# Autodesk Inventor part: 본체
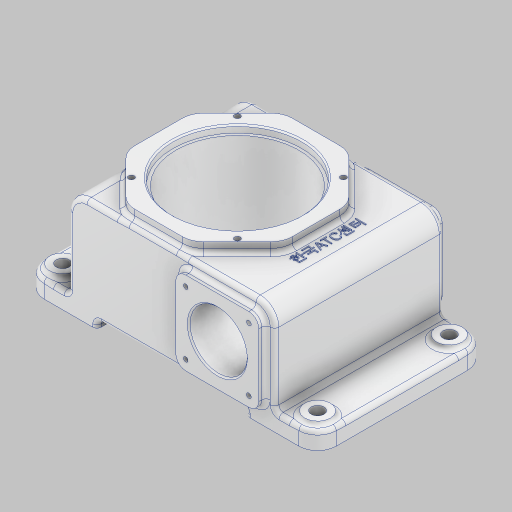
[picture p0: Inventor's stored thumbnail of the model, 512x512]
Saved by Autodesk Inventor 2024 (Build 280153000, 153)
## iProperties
Created: 2026-02
Part Number: 본체
Material: 알루미늄 6061
Document SubType Name: Modeling
Designer: 2-10
Density: 2.7 g/cm^3
Appearance: 알루미늄 - 평지
Mass: 2338.38 g
Surface Area: 1210.62 cm^2
Volume: 866.066 cm^3
Author: 2-10
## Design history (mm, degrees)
sketch "스케치1"
  geometry: L1 (-72, -35)-(72, -35); L2 (72, -35)-(72, 35); L3 (72, 35)-(-72, 35); L4 (-72, 35)-(-72, -35); L5 (-72, -35)-(72, 35); L6 (72, -35)-(-72, 35); L7 (-102, -28)-(-52, -28); L8 (-52, -28)-(-52, -40); L9 (-52, -40)-(-102, -40); L10 (-102, -40)-(-102, -28); L11 (-102, -28)-(-52, -40); L12 (-52, -28)-(-102, -40); L13 (52, -28)-(102, -28); L14 (102, -28)-(102, -40); L15 (102, -40)-(52, -40); L16 (52, -40)-(52, -28); L17 (52, -28)-(102, -40); L18 (102, -28)-(52, -40); 6 further points
  constraints: 36 end point, 8 midpoint, 6 parallel, 3 horizontal, 3 perpendicular, 2 equal length, 1 coincident
  dimensions: "d0" = 144 distance of L3.end L2.end; "d1" = 70 distance of L2.end L1.end; "d3" = 50 distance between parallel lines of L8 L10; "d6" = 204 distance between parallel lines of L14 L10; "d7" = 30 distance between parallel lines of L14 L2; "d42" = 5 distance between parallel lines of L1 L15; "d43" = 12 distance between parallel lines of L13 L15; "d44" = 5 distance between parallel lines of L1 L9
extrude "돌출1" new body sketch "스케치1" stored distance "d8" = 118; taper "d9" = 0 deg
extrude "돌출2" join sketch "스케치1" stored distance "d10" = 118; taper "d11" = 0 deg
sketch "스케치2"
  geometry: L1 (52, -40)-(102, -40) reference; L2 (102, -28)-(72, -28) reference; L3 (15, -29)-(59, -29); L4 (66, -22)-(66, 22); L5 (59, 29)-(15, 29); L6 (8, 22)-(8, -22); L7 (8, -29)-(66, 29); L8 (66, -29)-(8, 29); L9 (102, -40)-(102, -28) reference; A1 r 7 centre (15, 22) between (15, 29) and (8, 22); A2 r 7 centre (15, -22) between (8, -22) and (15, -29); A3 r 7 centre (59, -22) between (59, -29) and (66, -22); A4 r 7 centre (59, 22) between (66, 22) and (59, 29); 4 further points
  constraints: 12 end point, 8 point on circle, 8 point on line, 8 tangent, 4 centre point, 4 midpoint, 3 equal radius, 2 parallel, 1 horizontal, 1 perpendicular
  dimensions: "d12" = 58 distance of L8.end L7.end; "d13" = 58 distance of L7.end L8.start; "d14" = 40 distance from line of point (37, 0) L1; "d16" = 7 radius of A1; "d137" = 65 distance from line of point (37, 29) L9
extrude "돌출3" join sketch "스케치2" distance "d17" = 5; taper "d18" = 0 deg
sketch "스케치3"
  geometry: L1 (8.393, 86.175)-(31.825, 109.607); L2 (42.431, 114)-(75.569, 114); L3 (86.175, 109.607)-(109.607, 86.175); L4 (114, 75.569)-(114, 42.431); L5 (109.607, 31.825)-(86.175, 8.393); L6 (75.569, 4)-(42.431, 4); L7 (31.825, 8.393)-(8.393, 31.825); L8 (4, 42.431)-(4, 75.569); L9 (131, 123)-(87, 123) reference; L10 (131, -5)-(87, -5) reference; L11 (-30, 118)-(-30, 0) reference; A1 r 15 centre (42.431, 19) between (31.825, 8.393) and (42.431, 4); A2 r 15 centre (19, 42.431) between (4, 42.431) and (8.393, 31.825); A3 r 15 centre (19, 75.569) between (8.393, 86.175) and (4, 75.569); A4 r 15 centre (42.431, 99) between (42.431, 114) and (31.825, 109.607); A5 r 15 centre (75.569, 99) between (86.175, 109.607) and (75.569, 114); A6 r 15 centre (99, 75.569) between (114, 75.569) and (109.607, 86.175); A7 r 15 centre (99, 42.431) between (109.607, 31.825) and (114, 42.431); A8 r 15 centre (75.569, 19) between (75.569, 4) and (86.175, 8.393); 13 further points
  constraints: 16 end point, 16 point on circle, 16 point on line, 16 tangent, 8 centre point, 7 equal radius, 4 midpoint, 1 horizontal alignment, 1 vertical, 17 other
  dimensions: "d31" = 15 radius of A1; "d138" = 50 horizontal distance of point (59, 59) point (109, -5); "d141" = 110 distance between parallel lines of L2 L6
extrude "돌출4" join sketch "스케치3" distance "d32" = 7; taper "d33" = 0 deg
sketch "스케치4"
  geometry: L1 (59, 29)-(15, 29) reference; L2 (15, -29)-(59, -29) reference; L3 (8, 22)-(8, -22) reference; L4 (59, 29)-(15, 29) reference; L5 (66, -22)-(66, 22) reference; L6 (-13, 76.49)-(-13, -76.49); L7 (-63.607, 42)-(-40.175, 42) reference; L8 (-29.569, 42)-(-40.175, 42) reference; L9 (-29.569, 42)-(3.569, 42) reference; L10 (14.175, 42)-(3.569, 42) reference; L11 (14.175, 42)-(37.607, 42) reference; L12 (42, 42)-(37.607, 42) reference; L13 (-63.607, 42)-(-68, 42) reference; L14 (-58, 42)-(-58, 37); L15 (-58, 37)-(-56, 37); L16 (-56, 37)-(-56, -24); L17 (-56, -24)-(-13, -24); A1 r 7 centre (59, -22) between (59, -29) and (66, -22) reference; A2 r 7 centre (15, -22) between (8, -22) and (15, -29) reference; A3 r 7 centre (15, 22) between (15, 29) and (8, 22) reference; A4 r 7 centre (59, 22) between (66, 22) and (59, 29) reference; 5 further points
  constraints: 10 end point, 3 perpendicular, 2 midpoint, 2 point on line, 2 vertical, 1 horizontal alignment
  dimensions: "d34" = 50 distance from line of L6 point (37, -29); "d35" = 90 diameter of L14 L6; "d36" = 86 diameter of L16 L6; "d37" = 5 distance between parallel lines of L15 L7; "d38" = 66 distance between parallel lines of L17 L7
revolve "회전1" sketch "스케치4" stored, may be unused: angle "d45" = 90 deg
sketch "스케치5"
  geometry: L1 (30, -24)-(-56, -24) reference; L2 (-13, 15.405)-(-13, -63.405); L3 (-58, 42)-(32, 42) reference; L4 (-13, -18)-(12, -18); L5 (12, -18)-(18, -24); 2 further points
  constraints: 6 end point, 2 midpoint, 2 point on line, 1 horizontal, 1 vertical
  dimensions: "d48" = 6 distance between parallel lines of L4 L1; "d49" = 45 deg angle of L2 L5; "d50" = 50 diameter of L4.end L2
revolve "회전2" sketch "스케치5" stored, may be unused: angle "d51" = 90 deg
sketch "스케치6"
  geometry: L1 (-13, 36)-(-13, -72); L2 (-38, -18)-(12, -18) reference; L3 (-33, -18)-(-33, -27.5); L4 (-31.5, -29)-(-13, -29); A1 r 1.5 centre (-31.5, -27.5) between (-33, -27.5) and (-31.5, -29); 3 further points
  constraints: 6 end point, 4 point on line, 2 midpoint, 2 point on circle, 2 tangent, 2 vertical, 1 centre point, 1 perpendicular
  dimensions: "d52" = 40 diameter of L3 L1; "d53" = 11 distance between parallel lines of L2 L4; "d55" = 1.5 radius of A1
revolve "회전3" sketch "스케치6" stored, may be unused: angle "d54" = 90 deg
sketch "스케치7"
  geometry: L1 (59, 29)-(15, 29) reference; L2 (8, 22)-(8, -22) reference; C1 r 20 at (37, 0); 3 further points
  constraints: 2 midpoint, 1 centre point, 1 horizontal alignment, 1 vertical alignment
  dimensions: "d56" = 40 diameter of C1
extrude "돌출5" cut sketch "스케치7" extent not by distance; stored distance "d57" = 0; taper "d58" = 0 deg
fillet "모깎기19" dims "d135" = 13
fillet "모깎기1" dims "d59" = 13
fillet "모깎기3" dims "d61" = 3
sketch "스케치10"
  geometry: L1 (0, 7)-(44, 7); L2 (44, 7)-(44, 51); L3 (44, 51)-(0, 51); L4 (0, 51)-(0, 7); L5 (0, 7)-(44, 51); L6 (44, 7)-(0, 51); C1 r 20 at (22, 29) reference; 5 further points
  constraints: 12 end point, 4 coincident, 2 midpoint, 2 parallel, 1 horizontal, 1 perpendicular
  dimensions: "d88" = 44 distance of L3.end L2.end; "d89" = 44 distance of L2.end L1.end
hole "구멍2" sketch "스케치10" at (0, 51), (44, 51), (0, 7), (44, 7) diameter "d81" = 3.242; stored, may be unused: countersink angle "d85" = 90 deg, drill point angle "d87" = 118 deg; dims "d82" = 8, "d83" = 4, "d84" = 2, "d86" = 10
sketch "스케치11"
  geometry: L1 (96, 22)-(22, 22); L2 (22, 22)-(22, 96); L3 (22, 96)-(96, 96); L4 (96, 96)-(96, 22); L5 (96, 22)-(22, 96); L6 (22, 22)-(96, 96); C1 r 45 at (59, 59) reference; 5 further points
  constraints: 12 end point, 4 coincident, 2 midpoint, 2 parallel, 1 horizontal, 1 perpendicular
  dimensions: "d97" = 74 distance of L2.end L3.end; "d98" = 74 distance of L1.end L2.end
hole "구멍3" sketch "스케치11" at (22, 22), (22, 96), (96, 22), (96, 96) diameter "d90" = 4.134; stored, may be unused: countersink angle "d94" = 90 deg, drill point angle "d96" = 118 deg; dims "d91" = 10, "d92" = 4, "d93" = 2, "d95" = 12
sketch "스케치12"
  geometry: C1 r 9 at (13, 92); C2 r 9 at (13, 0); C3 r 9 at (191, 92); C4 r 9 at (191, 0); A1 r 13 centre (13, 92) between (13, 105) and (0, 92) reference; A2 r 13 centre (13, 0) between (0, 0) and (13, -13) reference; A3 r 13 centre (191, 92) between (204, 92) and (191, 105) reference; A4 r 13 centre (191, 0) between (191, -13) and (204, 0) reference; 1 further point
  constraints: 4 centre point, 4 concentric
  dimensions: "d99" = 18 diameter of C1; "d100" = 18 diameter of C2; "d101" = 18 diameter of C4; "d102" = 18 diameter of C3
extrude "돌출7" join sketch "스케치12" distance "d103" = 3; taper "d104" = 0 deg
fillet "모깎기5" dims "d105" = 3
fillet "모깎기7" dims "d107" = 3
fillet "모깎기8" dims "d108" = 3
fillet "모깎기11" dims "d111" = 3
chamfer "모따기1" distance "d114" = 1; stored, may be unused: second distance "d115" = 2, angle "d116" = 45 deg
fillet "모깎기14" dims "d117" = 3
chamfer "모따기2" distance "d118" = 1; stored, may be unused: second distance "d119" = 2, angle "d120" = 45 deg
sketch "스케치13"
  geometry: C1 r 9 at (0, 0) reference; C2 r 9 at (0, 92) reference; C3 r 9 at (-178, 0) reference; C4 r 9 at (-178, 92) reference; 5 further points
  constraints: 4 coincident
hole "구멍4" sketch "스케치13" at (0, 0), (0, 92), (-178, 0), (-178, 92) diameter "d121" = 9; stored, may be unused: countersink angle "d125" = 90 deg, drill point angle "d127" = 0 deg; dims "d122" = 10, "d123" = 4, "d124" = 2, "d126" = 12
node "작업 평면3"
sketch "스케치14"
  geometry: C1 r 18.5 at (-58, 16.569) reference; 2 further points
  constraints: 1 horizontal alignment, 1 other
  dimensions: "d128" = 65 distance of C1.centre point (7, 16.569)
feature "엠보싱1" dims "d0" = 144, "d1" = 70, "d3" = 50, "d6" = 204, "d7" = 30, "d42" = 5, "d43" = 12, "d44" = 5, "d132" = 0.5, "d133" = 0
fillet "모깎기20" dims "d136" = 3
fillet "모깎기21" dims "d140" = 3
node "솔리드1"
mirror "미러1"
mirror "미러2"
node "투영된 루프1"
feature "A9D066F2-1C7D-4E18-AEED-F7BC21143FA4" dims "d81" = 3.242, "d82" = 8, "d83" = 4, "d84" = 2, "d85" = 90 deg, "d86" = 10, "d87" = 118 deg
